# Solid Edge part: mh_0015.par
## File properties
Title: grip_r_f
Author: edge
Template: normal.par
Last saved by: edge
Revision: 35
Application: Solid Edge
Material: ABS
非切断部品: False
文書内容のタイプ: 0
Density: 0.001200 g/mm^3
Accuracy: 0.99
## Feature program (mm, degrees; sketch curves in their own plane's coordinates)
sketch for "unnamed Protrusion 1" plane through (0, 0, 0) normal (0, 0, 1) x-axis (1, 0, 0)
  line (0, 0) -> (0, -80)
  line (0, -80) -> (-50, -80)
  line (-50, -80) -> (-50, 0)
  line (-50, 0) -> (0, 0)
extrude "unnamed Protrusion 1" add finite 15 along +normal
thinwall "Thinwall_1"  Thickness = 1 mm
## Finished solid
Body 1: solid body, 11 faces, 24 edges, 16 vertices.
  Faces by surface: plane 11
  Edges by curve: line 24
Bounding box of the edges (mm): 50.000 x 80.000 x 15.000, from (-50, -80, 0) to (0, 0, 15).
Planar faces by outward normal: +x 2, +y 2, +z 1, -x 2, -y 2, -z 2
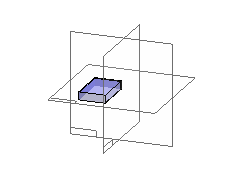
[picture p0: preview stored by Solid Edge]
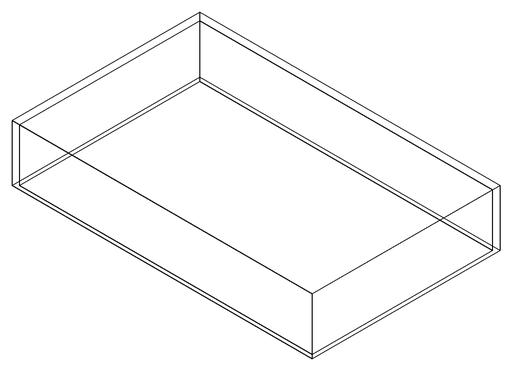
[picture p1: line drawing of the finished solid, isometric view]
